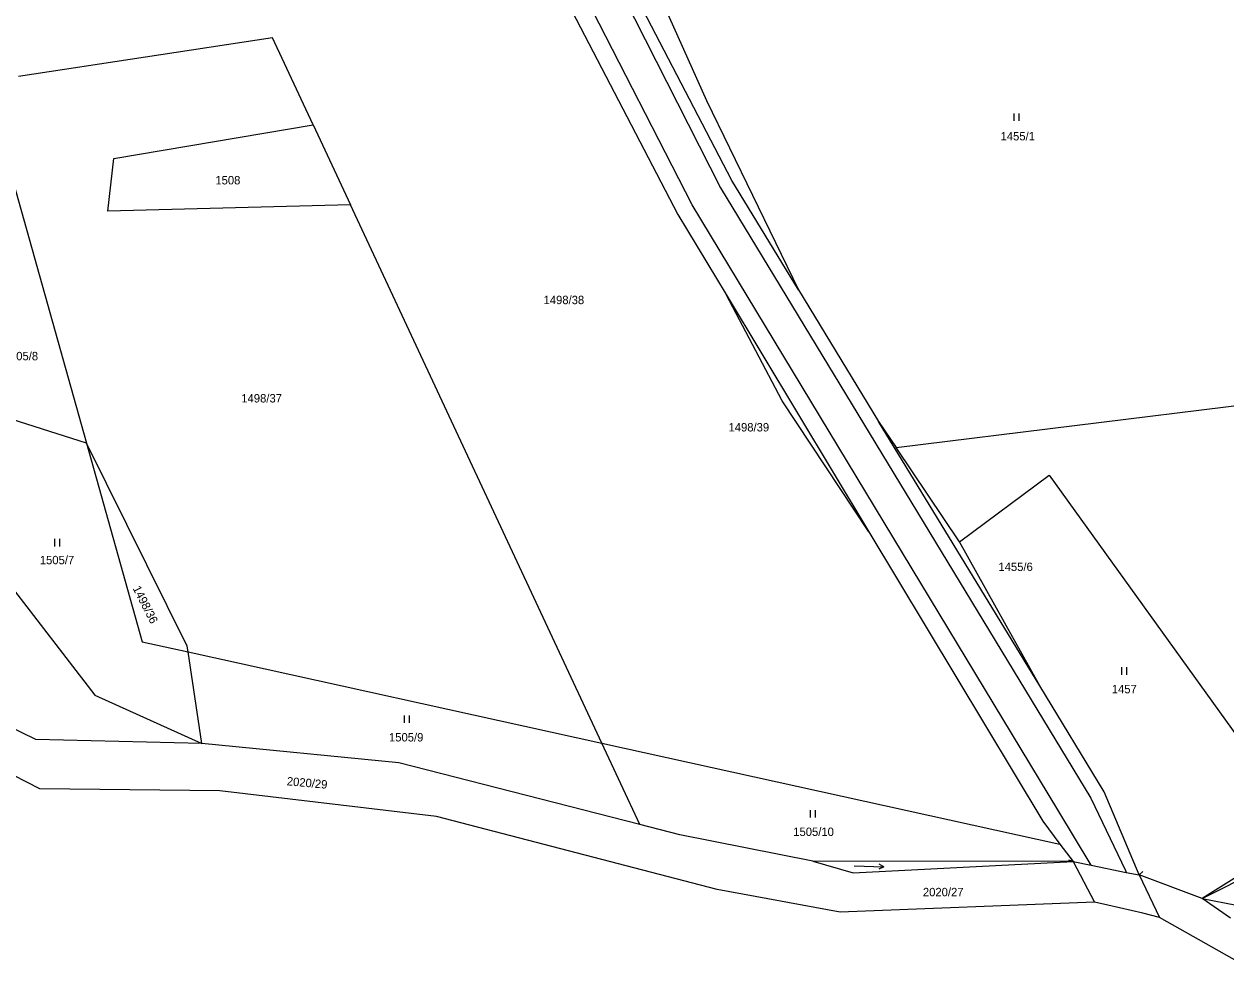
# Model space of a CAD drawing. Extents: x -793666 to -785424, y -1118958 to -1108761.
# Drawn here: x -787806.2 to -787563.2, y -1118496.5 to -1118305 of the extents above; entities that cross this region are included whole.
import ezdxf

# ---------------------------------------------------------------- set-up
doc = ezdxf.new("R2010")
doc.units = 0
for name, color, linetype in [('Hranice parcel', 7, 'Continuous'), ('Parcelní čísla', 7, 'Continuous'), ('Vnitřní kresba', 7, 'Continuous'), ('Značky kultur', 7, 'Continuous')]:
    doc.layers.add(name, color=color, linetype=linetype)

msp = doc.modelspace()

# ---------------------------------------------------------------- linework, layer by layer
at = {"layer": 'Hranice parcel'}
for p, q in [((-787747.73, -1118325.4), (-787740.19, -1118341.58)), ((-787808.86, -1118335.23), (-787793.56, -1118389.75)), ((-787689.36, -1118450.41), (-787740.19, -1118341.58)), ((-787664.25, -1118359.72), (-787635.36, -1118407.71)), ((-787649.61, -1118358.77), (-787633.4, -1118385.37)), ((-787629.87, -1118390.63), (-787438.82, -1118367.18)), ((-787793.56, -1118389.75), (-787817.84, -1118382.05)), ((-787600.82, -1118438.83), (-787633.4, -1118385.37)), ((-787633.4, -1118385.37), (-787629.87, -1118390.63)), ((-787617.06, -1118409.72), (-787629.87, -1118390.63)), ((-787600.82, -1118438.83), (-787617.06, -1118409.72)), ((-787770.25, -1118450.47), (-787773.05, -1118431.97)), ((-787773.05, -1118431.97), (-787689.36, -1118450.41)), ((-787681.67, -1118466.88), (-787689.36, -1118450.41)), ((-787689.36, -1118450.41), (-787596.72, -1118470.83)), ((-787546.81, -1118468.61), (-787568, -1118481.84)), ((-787596.72, -1118470.83), (-787594.04, -1118474.37)), ((-787594.04, -1118474.37), (-787646.67, -1118474.26)), ((-787568, -1118481.84), (-787580.73, -1118477.06)), ((-787562.27, -1118485.78), (-787568, -1118481.84)), ((-787557.53, -1118496.48), (-787576.6, -1118485.68))]:
    msp.add_line(p, q, dxfattribs=at)
for points in [[(-787649.61, -1118358.77), (-787663.06, -1118336.69), (-787686.98, -1118290.64), (-787692.22, -1118272.57), (-787694.05, -1118257.78), (-787694.33, -1118249.63)], [(-787691.19, -1118253.39), (-787686.69, -1118277.22), (-787677.74, -1118299.04), (-787668.17, -1118320.47), (-787649.61, -1118358.77)], [(-787697.98, -1118297.34), (-787673.98, -1118343.56), (-787664.25, -1118359.72)], [(-787747.73, -1118325.4), (-787755.97, -1118307.8), (-787807.3, -1118315.64)], [(-787740.19, -1118341.58), (-787789.28, -1118342.84), (-787788.02, -1118332.18), (-787747.73, -1118325.4)], [(-787635.36, -1118407.71), (-787652.87, -1118381.21), (-787664.25, -1118359.72)], [(-787773.05, -1118431.97), (-787773.22, -1118430.81), (-787793.56, -1118389.75)], [(-787793.56, -1118389.75), (-787782.29, -1118429.93), (-787773.05, -1118431.97)], [(-787617.06, -1118409.72), (-787598.89, -1118396.21), (-787546.81, -1118468.61)], [(-787821.96, -1118401.79), (-787791.92, -1118440.7), (-787770.25, -1118450.47)], [(-787635.36, -1118407.71), (-787600.16, -1118466.19), (-787596.72, -1118470.83)], [(-787770.25, -1118450.47), (-787803.85, -1118449.67), (-787832.47, -1118435.72)], [(-787580.73, -1118477.06), (-787587.77, -1118460.25), (-787600.82, -1118438.83)], [(-787568, -1118481.84), (-787545.35, -1118470.42), (-787530.31, -1118463.17), (-787512.07, -1118444.65), (-787505.48, -1118439.7)], [(-787589.76, -1118482.59), (-787641.14, -1118484.57), (-787666.06, -1118480.04), (-787722.77, -1118465.26), (-787766.6, -1118460.09), (-787802.99, -1118459.64), (-787835.56, -1118443.04)], [(-787681.67, -1118466.88), (-787730.41, -1118454.38), (-787770.25, -1118450.47)], [(-787568, -1118481.84), (-787560.99, -1118483.15), (-787535.23, -1118466.77), (-787518.2, -1118456.82)], [(-787646.67, -1118474.26), (-787673.59, -1118468.95), (-787681.67, -1118466.88)], [(-787646.67, -1118474.26), (-787638.54, -1118476.62), (-787594.04, -1118474.37)], [(-787594.04, -1118474.37), (-787590.38, -1118475.11), (-787583.32, -1118476.54), (-787580.73, -1118477.06)], [(-787576.6, -1118485.68), (-787579.98, -1118484.8), (-787587.06, -1118483.17), (-787589.76, -1118482.59)]]:
    msp.add_lwpolyline(points, dxfattribs=at)
at = {"layer": 'Vnitřní kresba'}
for p, q in [((-787688.79, -1118291.92), (-787665.39, -1118338.11)), ((-787671.11, -1118341.57), (-787694.79, -1118295.3)), ((-787665.39, -1118338.11), (-787590.5, -1118461.56)), ((-787597.13, -1118463.88), (-787671.11, -1118341.57)), ((-787590.5, -1118461.56), (-787583.47, -1118476.16)), ((-787590.38, -1118475.11), (-787597.13, -1118463.88)), ((-787594.97, -1118474), (-787594.04, -1118474.37)), ((-787594.04, -1118474.37), (-787589.76, -1118482.59)), ((-787583.47, -1118476.16), (-787583.32, -1118476.54)), ((-787579.97, -1118476.4), (-787580.73, -1118477.06)), ((-787580.73, -1118477.06), (-787576.6, -1118485.68))]:
    msp.add_line(p, q, dxfattribs=at)
at = {"layer": 'Značky kultur'}
for p, q in [((-787605.99, -1118324.59), (-787605.99, -1118323.09)), ((-787604.99, -1118324.59), (-787604.99, -1118323.09)), ((-787799.98, -1118410.64), (-787799.98, -1118409.14)), ((-787798.98, -1118410.64), (-787798.98, -1118409.14)), ((-787584.21, -1118436.58), (-787584.21, -1118435.08)), ((-787583.21, -1118436.58), (-787583.21, -1118435.08)), ((-787729.27, -1118446.32), (-787729.27, -1118444.82)), ((-787728.27, -1118446.32), (-787728.27, -1118444.82)), ((-787647.17, -1118465.44), (-787647.17, -1118463.94)), ((-787646.17, -1118465.44), (-787646.17, -1118463.94)), ((-787638.32, -1118475.21), (-787632.33, -1118475.42)), ((-787632.33, -1118475.42), (-787633.32, -1118475.89)), ((-787632.33, -1118475.42), (-787633.28, -1118474.89))]:
    msp.add_line(p, q, dxfattribs=at)

# ---------------------------------------------------------------- texts
at = {"layer": 'Parcelní čísla'}
for s, p in [('1455/1', (-787608.73, -1118328.55)), ('1508', (-787767.52, -1118337.45)), ('1498/38', (-787701.15, -1118361.66)), ('1505/8', (-787810.32, -1118373.01)), ('1498/37', (-787762.27, -1118381.54)), ('1498/39', (-787663.75, -1118387.4)), ('1505/7', (-787803.02, -1118414.25)), ('1455/6', (-787609.17, -1118415.62)), ('1457', (-787586.25, -1118440.34)), ('1505/9', (-787732.41, -1118450.08)), ('1505/10', (-787650.66, -1118469.19)), ('2020/27', (-787624.44, -1118481.38))]:
    msp.add_text(s, height=1.7, dxfattribs=at).set_placement(p)
for s, rotation, p in [('1498/36', 297, (-787784.29, -1118419.12)), ('2020/29', 355, (-787753.13, -1118458.93))]:
    msp.add_text(s, height=1.7, rotation=rotation, dxfattribs=at).set_placement(p)

doc.saveas('drawing.dxf')
